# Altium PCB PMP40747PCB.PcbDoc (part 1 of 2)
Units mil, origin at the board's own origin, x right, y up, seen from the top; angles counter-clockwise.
Board outline 2952.76 x 3937.01 mil, 2 copper layers (Top Layer, Bottom Layer), stack 62 mil thick; 109 components, 53 nets, 257 pads, 138 vias.
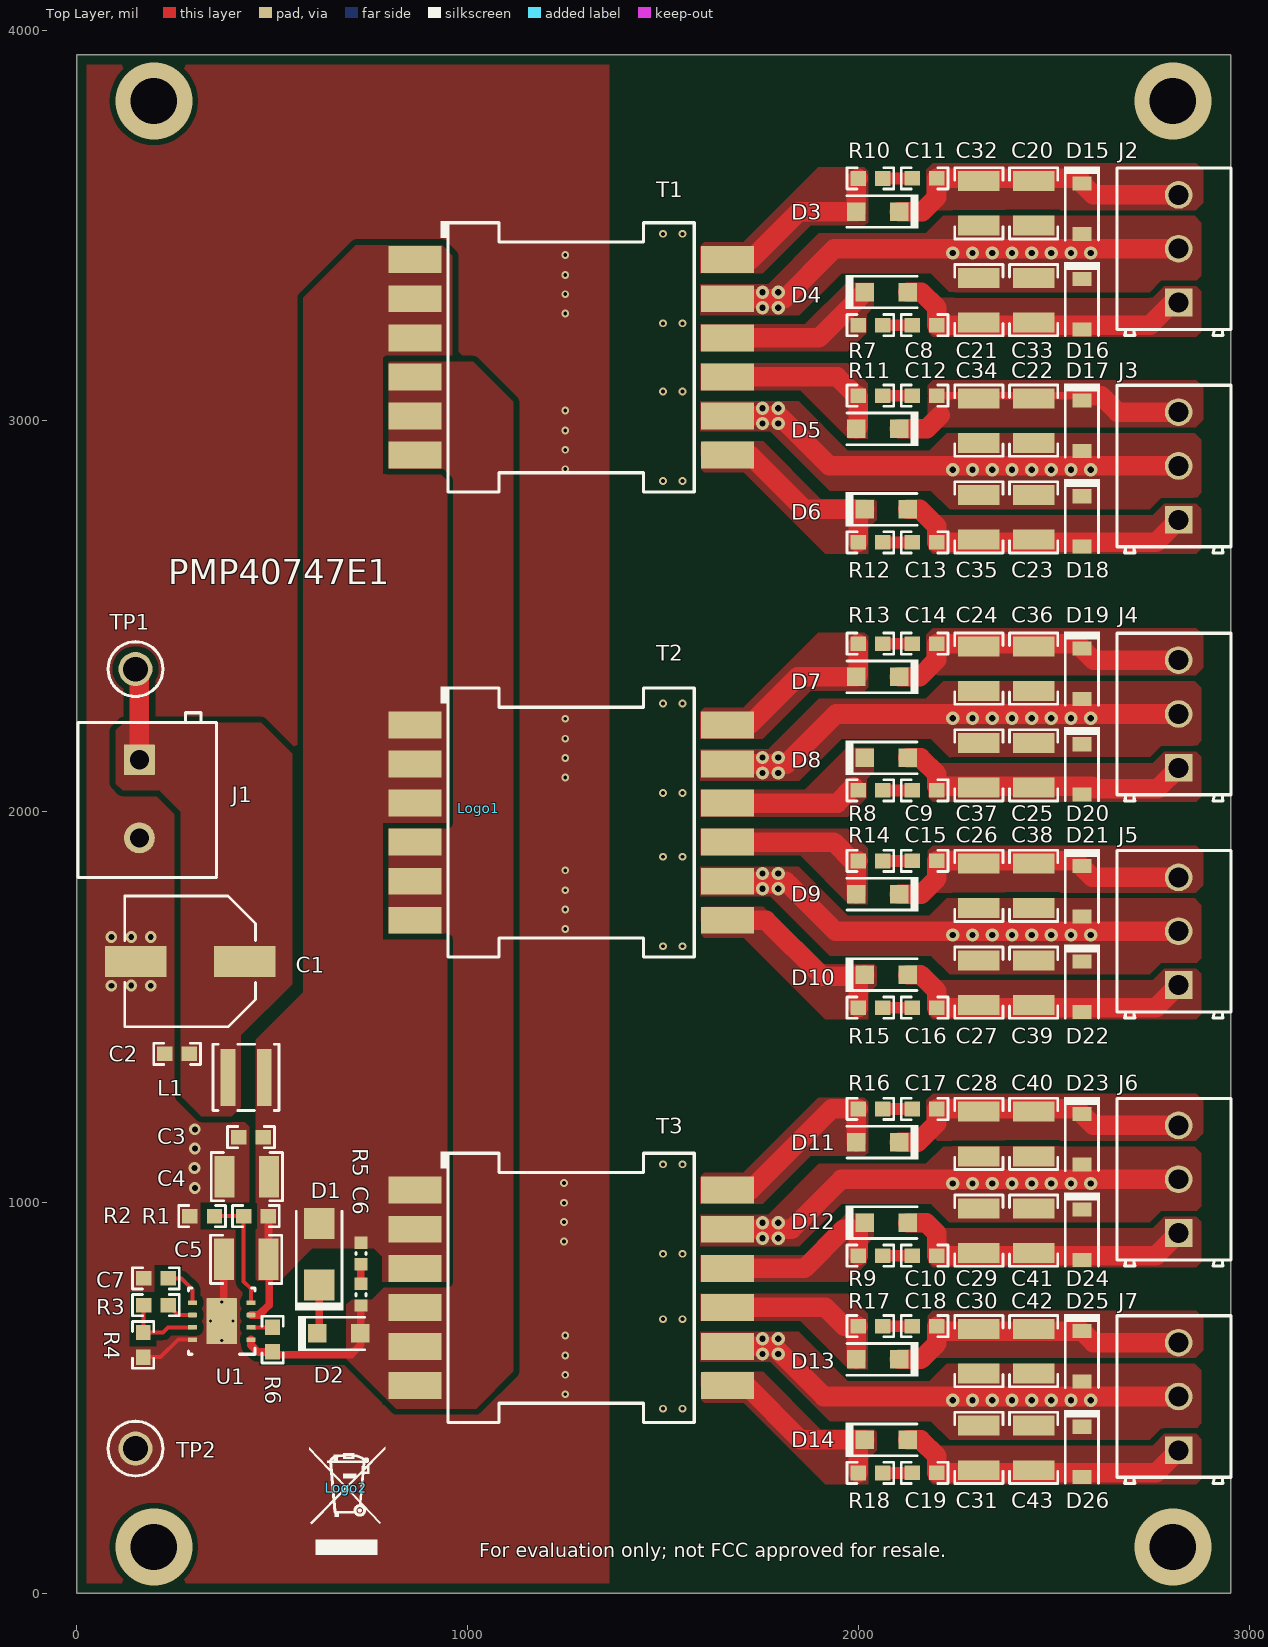
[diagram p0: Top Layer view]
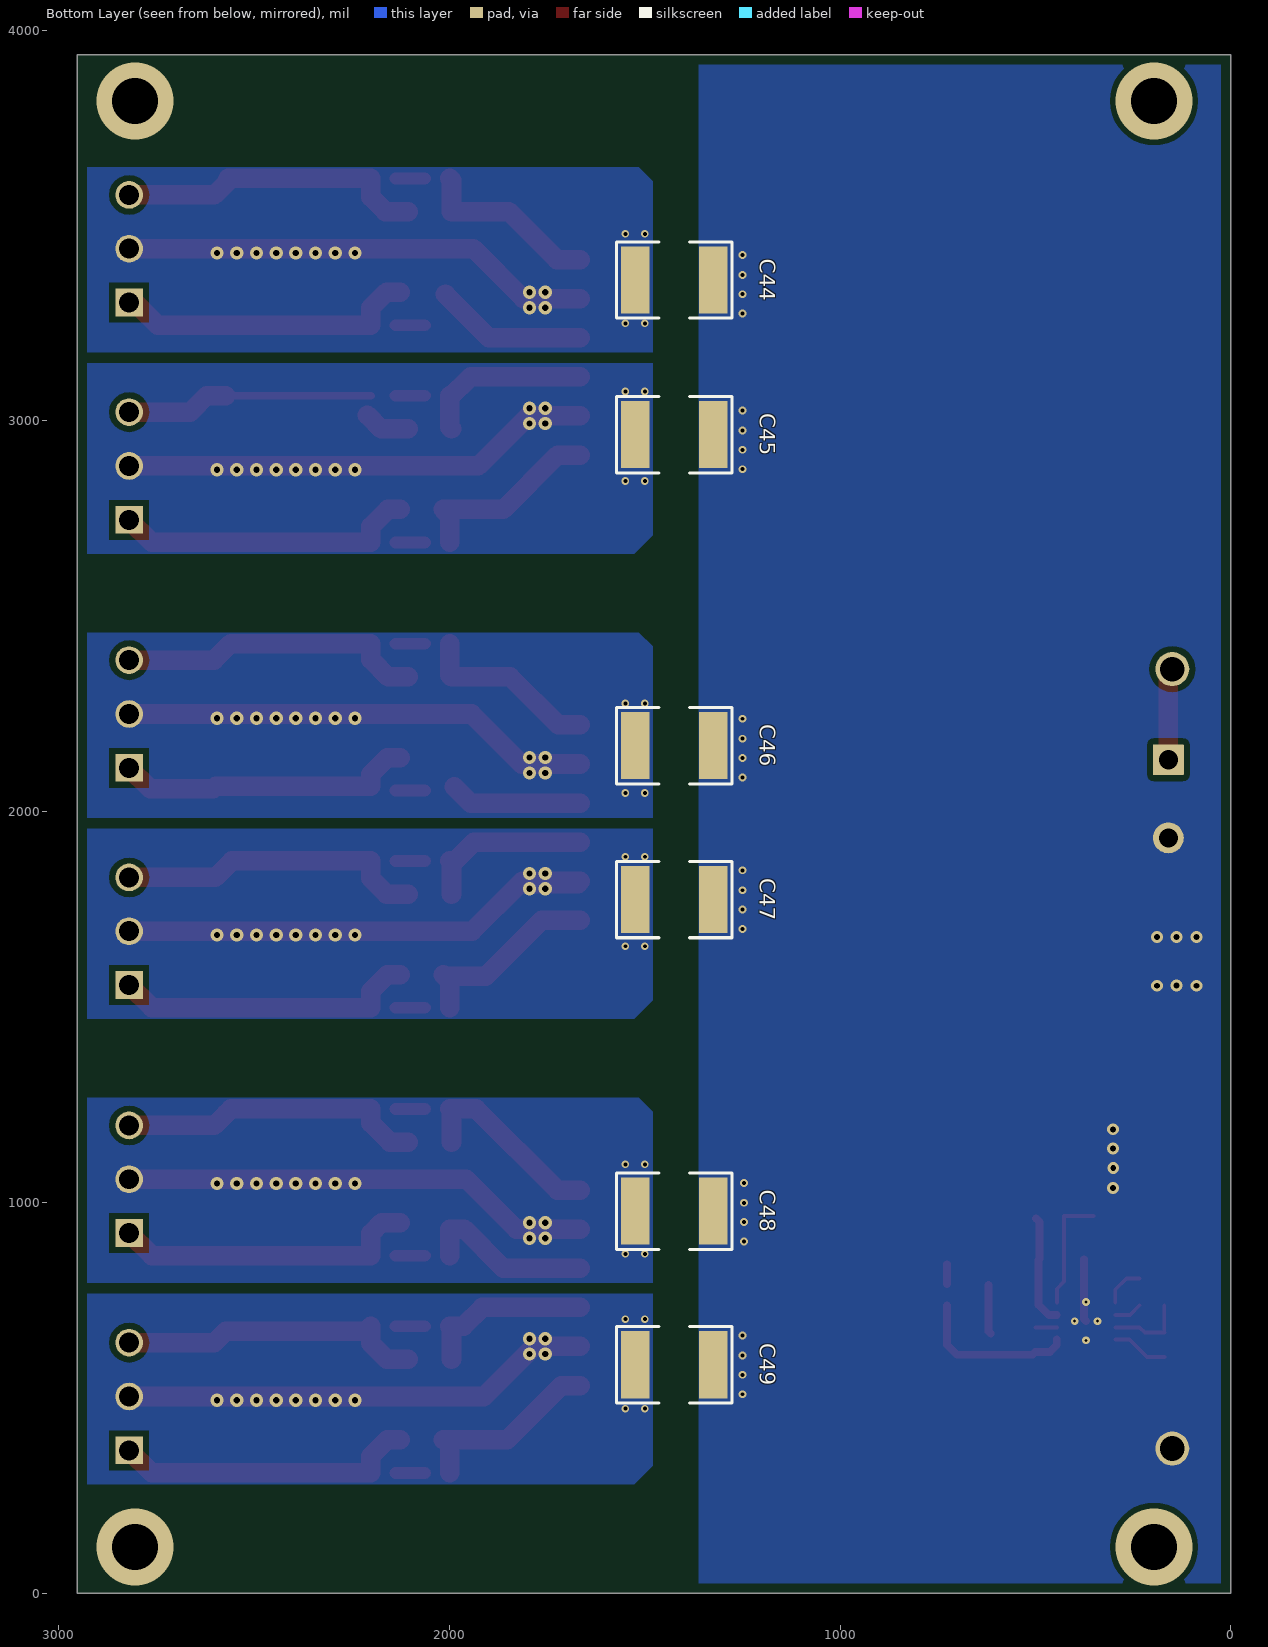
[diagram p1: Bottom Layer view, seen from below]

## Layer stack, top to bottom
Top Solder: solder mask 0.4, Solder Resist, Dk 3.5
Top Layer: signal copper 1.4
Dielectric1: core 59.2, FR-4, Dk 4.8
Bottom Layer: signal copper 1.4
Bottom Solder: solder mask 0.4, Solder Resist, Dk 3.5

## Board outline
0,0 0,3937.01 2952.76,3937.01 2952.76,0

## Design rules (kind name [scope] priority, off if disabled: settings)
AcuteAngle [All] p1: minimum=4.50000000000000E+0001 checktracksonly=FALSE
AssemblyTestPointUsage [All] p1: valid=2
BoardOutlineClearance BoardOutlineClearance_MountingHoles [OnCopper and InComponentClass('Mounting Holes')] p1: gap=39.37 ignorepadtopadclearanceinfootprint=FALSE
BoardOutlineClearance BoardOutlineClearance_Poly [OnCopper and IsPoly] p2: gap=25 ignorepadtopadclearanceinfootprint=FALSE
BoardOutlineClearance [OnCopper and Not InComponentClass('Logo') and not InComponentClass('FiducialMark') and not InRegion(1000,500,4000,800) and not InPoly] p3: gap=75 ignorepadtopadclearanceinfootprint=FALSE
Clearance Clearance_Keepouts [((IsTrack Or IsArc) And Not InPoly) And IsFree and IsKeepOut vs ((IsTrack Or IsArc) And Not InPoly) And IsFree and IsKeepOut] p1: gap=0 ignorepadtopadclearanceinfootprint=FALSE
Clearance Clearance_Poly [InPolygon] p2: gap=15 ignorepadtopadclearanceinfootprint=TRUE
Clearance Clearance_FiducialMark [IsKeepOut and InComponentClass('FiducialMark') vs IsPad and InComponentClass('FiducialMark')] p3: gap=0 ignorepadtopadclearanceinfootprint=FALSE
Clearance [All] p4: gap=7.87 ignorepadtopadclearanceinfootprint=TRUE
ComponentClearance ComponentClearance_MountingHoles_FiducialMarks [InComponentClass('Mounting Holes') vs InComponentClass('FiducialMark')] p1: gap=50 collisioncheckmode=3 verticalgap=10 showdistances=FALSE
ComponentClearance ComponentClearance_Shunt [InComponentClass('Header') vs InComponentClass('Shunt')] p2: gap=0 collisioncheckmode=3 verticalgap=0 showdistances=FALSE
ComponentClearance ComponentClearance_Logo [InComponentClass('Logo')] p3: gap=50 collisioncheckmode=3 verticalgap=10 showdistances=FALSE
ComponentClearance ComponentClearance_ScrewToNut [(HasFootprint('NY PMS 440 0025 PH')) vs (HasFootprint('Keystone_1902C'))] p4: gap=5 collisioncheckmode=3 verticalgap=10 showdistances=FALSE
ComponentClearance ComponentClearance_MountingHoles [InComponentClass('Mounting Holes')] p5: gap=250 collisioncheckmode=3 verticalgap=100000 showdistances=FALSE
ComponentClearance ComponentClearance_SmallPassives [HasFootprint('0201*') or HasFootprint('0402*') or HasFootprint('0508') or HasFootprint('0603*') or HasFootprint('0612') or HasFootprint('0805*') or HasFootprint('0815*') or HasFootprint('0830*') or HasFootprint('1206*') or HasFootprint('1210*') or HasFootprint('1808*') or HasFootprint('1812*') or HasFootprint('1825*') or HasFootprint('2010*') or HasFootprint('2220*') or HasFootprint('2225*') or HasFootprint('2512*') or HasFootprint('2728*') or HasFootprint('3518*') vs HasFootprint('0201*') or HasFootprint('0402*') or HasFootprint('0508') or HasFootprint('0603*') or HasFootprint('0612') or HasFootprint('0805*') or HasFootprint('0815*') or HasFootprint('0830*') or HasFootprint('1206*') or HasFootprint('1210*') or HasFootprint('1808*') or HasFootprint('1812*') or HasFootprint('1825*') or HasFootprint('2010*') or HasFootprint('2220*') or HasFootprint('2225*') or HasFootprint('2512*') or HasFootprint('2728*') or HasFootprint('3518*')] p6: gap=5 collisioncheckmode=3 verticalgap=5 showdistances=FALSE
ComponentClearance ComponentClearance_THtoSMT [IsThruComponent vs IsSMTComponent] p7: gap=40 collisioncheckmode=3 verticalgap=30 showdistances=FALSE
ComponentClearance ComponentClearance_THtoTH [IsThruComponent vs IsThruComponent] p8: gap=30 collisioncheckmode=3 verticalgap=30 showdistances=FALSE
ComponentClearance [All] p9: gap=5 collisioncheckmode=3 verticalgap=5 showdistances=FALSE
DiffPairsRouting [All] p1: maxlimit=100 minlimit=10 mostfreqgap=10 toplayer_minwidth=15 toplayer_maxwidth=15 toplayer_prefwidth=15 bottomlayer_minwidth=15 bottomlayer_maxwidth=15 bottomlayer_prefwidth=15 maxuncoupledlength=1000
FabricationTestPointUsage TestPointUsage [All] p1: valid=2 allowmultiple=FALSE
FabricationTestpoint Testpoint [All] p1: side=3 testpointundercomponent=TRUE minsize=40 maxsize=100 preferedsize=60 minholesize=0 maxholesize=40 preferedholesize=32 testpointgrid=1 allowsidetop=TRUE allowsidebottom=TRUE usegrid=TRUE gridtolerance=0.01
FanoutControl Fanout_LCC [IsLCC] p1: bgadir=Out bgaviamode=Centered fanoutstyle=Auto fanoutdirection=Alternating viagrid=1 // Fanout_LCC (Default Rule)
FanoutControl Fanout_BGA [IsBGA] p2: bgadir=Out bgaviamode=Centered fanoutstyle=Auto fanoutdirection=Alternating viagrid=1 // Fanout_BGA (Default Rule)
FanoutControl Fanout_Default [All] p4: bgadir=Out bgaviamode=Centered fanoutstyle=Auto fanoutdirection=Alternating viagrid=1 // Fanout_Default (Default Rule)
FanoutControl Fanout_Small [(CompPinCount < 5)] p5: bgadir=Out bgaviamode=Centered fanoutstyle=Auto fanoutdirection=OutThenIn viagrid=1 // Fanout_Small (Default Rule)
HoleSize [All] p1: absolutevalues=TRUE maxlimit=251 minlimit=7.87 maxpercent=80.000 minpercent=20.000
MinimumAnnularRing MinimumAnnularRing_ThermalPadVias [IsVia and InAnyComponent] p1: minimumring=5.91
MinimumAnnularRing [All] p2: minimumring=7.87
MinimumSolderMaskSliver MinimumSolderMaskSliver_Logo [InComponentClass('Logo') vs InComponentClass('Logo')] p1: minsoldermaskwidth=0.7
MinimumSolderMaskSliver [All] p2: minsoldermaskwidth=3.94
PlaneConnect [All] p1: planeconnectstyle=Relief reliefexpansion=10 reliefentries=4 reliefconductorwidth=10 reliefairgap=10
PolygonConnect [All] p1: connectstyle=Direct reliefconductorwidth=10 reliefentries=4 polygonreliefangle="90 Angle" airgapwidth=10
RoutingVias ThermalPadVias [IsVia and InAnyComponent] p1: holewidth=7.87 width=19.68 viastyle="Through Hole" minholewidth=7.87 minwidth=19.68 maxholewidth=12.99 maxwidth=23.62
RoutingVias [All] p2: holewidth=16 width=34 viastyle="Through Hole" minholewidth=7.87 minwidth=26 maxholewidth=40 maxwidth=65
SilkToBoardRegionClearance [Not ((IsComment or IsDesignator) And (Hide <> 'False')) and not InRegion(1000,500,4000,800)] p1:
SilkToSilkClearance SilkToSilkClearance_Pb-FreeLogo [(HasFootprint('Pb-Free_Overlay_Medium') OR HasFootprint('Pb-Free_Overlay_Small')) vs (HasFootprint('Pb-Free_Overlay_Medium') OR HasFootprint('Pb-Free_Overlay_Small'))] p1: silktosilkclearance=0
SilkToSilkClearance [All] p2: silktosilkclearance=3.94
SilkToSolderMaskClearance SilkToComponentPadClearance [(IsPad or IsFill or IsRegion) and InAnycomponent] p1: minsilkscreentomaskgap=5 clearancetoexposedcopper=TRUE
SilkToSolderMaskClearance "Silk to Solder Mask Opening" [All] p2: minsilkscreentomaskgap=3.94 clearancetoexposedcopper=FALSE
SolderMaskExpansion [All] p1: expansion=1.97
UnRoutedNet [All] p1: checkbadconnections=TRUE
Width [All] p1: maxlimit=100 minlimit=6 preferedwidth=10 checkconnectedcopper=TRUE
14 further rules are at their usual default settings.

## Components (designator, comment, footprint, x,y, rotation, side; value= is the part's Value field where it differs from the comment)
C1 "EEE-FK1E221P" SM_RADIAL_F 290.02,1616.65 r180 top value=220uF
C2 "CGA3E2X7R1H104K080AA" 0603 256.58,1380 r180 top value=0.1uF
C3 "CGA3E2X7R1H104K080AA" 0603 445.53,1166.94 r180 top value=0.1uF
C4 "UMJ325KB7106KMHT" 1210_270 435,1065.94 r180 top value=10uF
C5 "UMJ325KB7106KMHT" 1210_270 433.07,854.42 r180 top value=10uF
C6 "AC0603JRNPOYBN220" 0603L 726.67,763.87 r270 top value=22pF
C7 "CGA3E2X7R1H473K080AA" 0603 202.2,805.55 r180 top value=0.047uF
C8 "CGA3E2X7R2A102K080AA" 0603 2169.62,3245.28 r180 top value=1000pF
C9 "CGA3E2X7R2A102K080AA" 0603 2169.62,2054.46 r180 top value=1000pF
C10 "CGA3E2X7R2A102K080AA" 0603 2169.62,863.58 r180 top value=1000pF
C11 "CGA3E2X7R2A102K080AA" 0603 2169.62,3620.82 r180 top value=1000pF
C12 "CGA3E2X7R2A102K080AA" 0603 2169.62,3064.78 r180 top value=1000pF
C13 "CGA3E2X7R2A102K080AA" 0603 2169.62,2689.24 r180 top value=1000pF
C14 "CGA3E2X7R2A102K080AA" 0603 2169.62,2429.94 r180 top value=1000pF
C15 "CGA3E2X7R2A102K080AA" 0603 2169.62,1873.97 r180 top value=1000pF
C16 "CGA3E2X7R2A102K080AA" 0603 2169.62,1498.43 r180 top value=1000pF
C17 "CGA3E2X7R2A102K080AA" 0603 2169.62,1239.12 r180 top value=1000pF
C18 "CGA3E2X7R2A102K080AA" 0603 2169.62,683.09 r180 top value=1000pF
C19 "CGA3E2X7R2A102K080AA" 0603 2169.62,307.61 r180 top value=1000pF
C20 "TMK325B7226MM-PR" 1210_270 2448.79,3556.82 r90 top value=22uF
C21 "TMK325B7226MM-PR" 1210_270 2308.34,3309.21 r270 top value=22uF
C22 "TMK325B7226MM-PR" 1210_270 2448.79,3000.78 r90 top value=22uF
C23 "TMK325B7226MM-PR" 1210_270 2448.79,2753.17 r270 top value=22uF
C24 "TMK325B7226MM-PR" 1210_270 2308.34,2366 r90 top value=22uF
C25 "TMK325B7226MM-PR" 1210_270 2448.79,2118.4 r270 top value=22uF
C26 "TMK325B7226MM-PR" 1210_270 2308.34,1809.97 r90 top value=22uF
C27 "TMK325B7226MM-PR" 1210_270 2308.34,1562.36 r270 top value=22uF
C28 "TMK325B7226MM-PR" 1210_270 2308.34,1175.19 r90 top value=22uF
C29 "TMK325B7226MM-PR" 1210_270 2308.34,927.58 r270 top value=22uF
C30 "TMK325B7226MM-PR" 1210_270 2308.34,619.15 r90 top value=22uF
C31 "TMK325B7226MM-PR" 1210_270 2308.34,371.54 r270 top value=22uF
C32 "TMK325B7226MM-PR" 1210_270 2308.34,3556.82 r90 top value=22uF
C33 "TMK325B7226MM-PR" 1210_270 2448.79,3309.21 r270 top value=22uF
C34 "TMK325B7226MM-PR" 1210_270 2308.34,3000.78 r90 top value=22uF
C35 "TMK325B7226MM-PR" 1210_270 2308.34,2753.17 r270 top value=22uF
C36 "TMK325B7226MM-PR" 1210_270 2448.79,2366 r90 top value=22uF
C37 "TMK325B7226MM-PR" 1210_270 2308.34,2118.4 r270 top value=22uF
C38 "TMK325B7226MM-PR" 1210_270 2448.79,1809.97 r90 top value=22uF
C39 "TMK325B7226MM-PR" 1210_270 2448.79,1562.36 r270 top value=22uF
C40 "TMK325B7226MM-PR" 1210_270 2448.79,1175.19 r90 top value=22uF
C41 "TMK325B7226MM-PR" 1210_270 2448.79,927.58 r270 top value=22uF
C42 "TMK325B7226MM-PR" 1210_270 2448.79,619.15 r90 top value=22uF
C43 "TMK325B7226MM-PR" 1210_270 2448.79,371.54 r270 top value=22uF
C44 "C1812C102KHRACAUTO" 1812_180 1425,3361 r180 bottom value=1000pF
C45 "C1812C102KHRACAUTO" 1812_180 1425,2965 r180 bottom value=1000pF
C46 "C1812C102KHRACAUTO" 1812_180 1425,2169 r180 bottom value=1000pF
C47 "C1812C102KHRACAUTO" 1812_180 1425,1775 r180 bottom value=1000pF
C48 "C1812C102KHRACAUTO" 1812_180 1425,977.54 r180 bottom value=1000pF
C49 "C1812C102KHRACAUTO" 1812_180 1425,584.51 r180 bottom value=1000pF
D1 "3SMAJ5936B-TP" SMA 620.09,867.54 r90 top value=30V
D2 "PMEG60T30ELRX" SOD-123W 670,664.64 r0 top value=60V
D3 "PMEG6010CEH,115" SOD-123F 2049.95,3536.04 r180 top value=60V
D4 "PMEG6010CEH,115" SOD-123F 2071.45,3329.99 r0 top value=60V
D5 "PMEG6010CEH,115" SOD-123F 2049.95,2980.01 r180 top value=60V
D6 "PMEG6010CEH,115" SOD-123F 2071.45,2773.95 r0 top value=60V
D7 "PMEG6010CEH,115" SOD-123F 2049.95,2345.23 r180 top value=60V
D8 "PMEG6010CEH,115" SOD-123F 2071.45,2137.61 r0 top value=60V
D9 "PMEG6010CEH,115" SOD-123F 2049.95,1789.19 r180 top value=60V
D10 "PMEG6010CEH,115" SOD-123F 2071.45,1583.14 r0 top value=60V
D11 "PMEG6010CEH,115" SOD-123F 2049.95,1154.41 r180 top value=60V
D12 "PMEG6010CEH,115" SOD-123F 2071.45,948.36 r0 top value=60V
D13 "PMEG6010CEH,115" SOD-123F 2049.95,598.38 r180 top value=60V
D14 "PMEG6010CEH,115" SOD-123F 2071.45,392.32 r0 top value=60V
D15 "DDZ16BQ-7" SOD-123 2572.35,3543.52 r270 top value=16V
D16 "DDZ8V2BQ-7" SOD-123 2572.35,3298.96 r270 top value=8.2V
D17 "DDZ16BQ-7" SOD-123 2572.35,2987.48 r270 top value=16V
D18 "DDZ8V2BQ-7" SOD-123 2572.34,2742.92 r270 top value=8.2V
D19 "DDZ16BQ-7" SOD-123 2572.35,2352.7 r270 top value=16V
D20 "DDZ8V2BQ-7" SOD-123 2572.35,2108.15 r270 top value=8.2V
D21 "DDZ16BQ-7" SOD-123 2572.35,1796.67 r270 top value=16V
D22 "DDZ8V2BQ-7" SOD-123 2572.35,1552.11 r270 top value=8.2V
D23 "DDZ16BQ-7" SOD-123 2572.34,1161.89 r270 top value=16V
D24 "DDZ8V2BQ-7" SOD-123 2572.35,917.33 r270 top value=8.2V
D25 "DDZ16BQ-7" SOD-123 2572.35,606.08 r270 top value=16V
D26 "DDZ8V2BQ-7" SOD-123 2572.35,361.29 r270 top value=8.2V
J1 "ED120/2DS" On-Shore_ED120_2DS 160,2032.8 r270 top
J2 "691214000000" Wurth_691214110003 2819.77,3440.89 r90 top
J3 "691214000000" Wurth_691214110003 2819.77,2884.85 r90 top
J4 "691214000000" Wurth_691214110003 2819.77,2250.07 r90 top
J5 "691214000000" Wurth_691214110003 2819.77,1694.04 r90 top
J6 "691214000000" Wurth_691214110003 2819.77,1059.26 r90 top
J7 "691214000000" Wurth_691214110003 2819.77,503.22 r90 top
L1 "XAL4030-332MEB" XAL4030 433.07,1320 r0 top value=3.3uH
Logo1 "FCC disclaimer" FCC_disclaimer 1028.98,2008.28 r0 top
Logo2 "WEEE logo" WEEE_Minimum 690,270 r0 top
R1 "CRCW0603140KFKEA" 0603 458.23,964.94 r0 top value=140k
R2 "CRCW060328K0FKEA" 0603 320.57,964.94 r0 top value=28.0k
R3 "CRCW0603348KFKEA" 0603 202.2,736.79 r0 top value=348k
R4 "CRCW060312K1FKEA" 0603 169.48,635.45 r90 top value=12.1k
R5 "CRCW0603100RFKEA" 0603L 726.67,869.18 r90 top value=100
R6 "CRCW0603232KFKEA" 0603 500.73,648.83 r270 top value=232k
R7 "CRCW060310R0FKEAHP" 0603 2030.94,3245.21 r0 top value=10.0
R8 "CRCW060310R0FKEAHP" 0603 2030.94,2054.4 r0 top value=10.0
R9 "CRCW060310R0FKEAHP" 0603 2030.94,863.58 r0 top value=10.0
R10 "CRCW060310R0FKEAHP" 0603 2030.94,3620.75 r0 top value=10.0
R11 "CRCW060310R0FKEAHP" 0603 2030.94,3064.72 r0 top value=10.0
R12 "CRCW060310R0FKEAHP" 0603 2030.94,2689.17 r0 top value=10.0
R13 "CRCW060310R0FKEAHP" 0603 2030.94,2429.94 r0 top value=10.0
R14 "CRCW060310R0FKEAHP" 0603 2030.94,1873.9 r0 top value=10.0
R15 "CRCW060310R0FKEAHP" 0603 2030.94,1498.36 r0 top value=10.0
R16 "CRCW060310R0FKEAHP" 0603 2030.94,1239.12 r0 top value=10.0
R17 "CRCW060310R0FKEAHP" 0603 2030.94,683.09 r0 top value=10.0
R18 "CRCW060310R0FKEAHP" 0603 2030.94,307.54 r0 top value=10.0
T1 "750344812" EFD15 1265.2,3162.87 r0 top value=45uH
T2 "750344812" EFD15 1265.2,1972.06 r0 top value=45uH
T3 "750344812" EFD15 1265.2,781.24 r0 top value=45uH
TP1 "5010" Keystone5010 150,2365 r0 top
TP2 "5011" Keystone5011 150,370 r0 top
U1 "LM25184QNGURQ1" NGU0008C 370.73,696.07 r180 top

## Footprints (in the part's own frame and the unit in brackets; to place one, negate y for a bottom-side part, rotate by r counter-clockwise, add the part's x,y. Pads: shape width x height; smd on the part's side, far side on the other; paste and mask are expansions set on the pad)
0603 [mm] "0603 from SM-752 data"
  rect 1x0.95 smd: 1(-0.8,0) 2(0.8,0)
  silkscreen extent -1.52,-0.69 1.52,0.69, body extent -0.87,-0.47 0.87,0.47, height 1
0603L [mm] "0603 from SM-752 data"
  rect 0.8x0.85 smd: 1(-0.7,0) 2(0.7,0)
  silkscreen extent -0.07,-0.33 0.07,0.33, body extent -0.87,-0.47 0.87,0.47, height 1
1210_270 [mm] "1210"
  rect 1.3x2.7 smd: 1(-1.45,0) 2(1.45,0)
  silkscreen extent -2.32,-1.57 2.32,1.57, body extent -1.7,-1.35 1.7,1.35, height 2.7
1812_180 [mm] "SMT, 2-Leads, Body 4.5x3.2mm"
  rect 1.85x4.36 smd: 1(-2.53,0) 2(2.53,0)
  silkscreen extent -3.75,-2.48 3.75,2.48, body extent -2.43,-1.75 2.42,1.75, height 1.8
EFD15 [mm] "SMT, 12-Leads, Body 17.5x16mm, Pitch 2.54mm"
  rect 3.43x1.75 smd: 1(-10.155,6.35) 2(-10.155,3.81) 3(-10.155,1.27) 4(-10.155,-1.27) 5(-10.155,-3.81) 6(-10.155,-6.35) 7(10.155,-6.35) 8(10.155,-3.81) 9(10.155,-1.27) 10(10.155,1.27) 11(10.155,3.81) 12(10.155,6.35)
  silkscreen extent -8.5,-8.75 8,8.85, body extent -11.05,-8.75 11.05,8.75, height 8.3
FCC_disclaimer [mil]
Keystone5010 [mil] "Keystone Multipurpose loops"
  round 87 hole 63: 1(0,0)
  silkscreen extent -70,-70 70,70, body extent -63,-63 63,62, height 319
Keystone5011 [mil] "Keystone Multipurpose loops"
  round 87 hole 63: 1(0,0)
  silkscreen extent -70,-70 70,70, body extent -63,-63 63,62, height 319
NGU0008C [mm] "SON, 8-Leads, Body 4x4mm, Pitch 0.8mm"
  rrect33% 0.6x0.3 smd: 1(-1.9,1.2) 2(-1.9,0.4) 3(-1.9,-0.4) 4(-1.9,-1.2) 5(1.9,-1.2) 6(1.9,-0.4) 7(1.9,0.4) 8(1.9,1.2)
  rrect8% 1.75x1.31 on Top Paste: 9(0,0.755) 9(0,-0.755)
  rrect5% 1.98x3 smd paste-1.5: 9(0,0)
  silkscreen extent -2.15,-2.15 2.15,2.15, body extent -2,-2 2,2, height 0.77
On-Shore_ED120_2DS [mm] "ONSHORE"
  rrect5% 2x2 hole 1.25: 1(-2.54,0)
  round 2 hole 1.25: 2(2.54,0)
  silkscreen extent -5.6,-4 5.12,5, body extent -5.78,-4 5.08,5, height 13
SM_RADIAL_F [mm] "8 x 10.2mm:  Panasonic F"
  rect 4x2 smd: 1(-3.55,0) 2(3.55,0)
  silkscreen extent -4.25,-4.25 4.25,4.25, body extent -4.25,-4.25 4.25,4.25, height 10.5
SMA [mm] "Molded Diode, 2-Leads, Body 4.3x2.6mm, IPC Medium Density, based on OnSemi component dimensions and land pattern"
  rect 2x2 smd: 1(-2,0) 2(2,0)
  silkscreen extent -3.66,-1.57 2.79,1.57, body extent -2.6,-1.3 2.6,1.3, height 2.42
SOD-123 [mm] "On Semi recommended land pattern"
  rect 0.915x1.22 smd: 1(-1.637,0) 2(1.637,0)
  silkscreen extent -2.74,-1.17 2.03,1.17, body extent -1.93,-0.9 1.93,0.9, height 1.35
SOD-123F [mm] "NXP recommended land pattern"
  rect 1.2x1.2 smd paste-0.05: 1(-1.4,0) 2(1.4,0)
  silkscreen extent -2.64,-1.12 2.01,1.12, body extent -1.8,-0.85 1.8,0.85, height 1.2
SOD-123W [mm] "NXP recommended land pattern"
  rect 1.2x1.2 smd paste-0.05: 1(-1.4,0) 2(1.4,0)
  silkscreen extent -2.64,-1.14 1.68,1.14, body extent -1.85,-0.95 1.85,0.95, height 1.1
WEEE_Minimum [mil] "WEEElie bin"
  silkscreen extent -95,-172 99,104
Wurth_691214110003 [mm] "Terminal Block, 3.5mm, 3x1, TH"
  rect 1.8x1.8 hole 1.3: 1(-3.5,0)
  round 1.8 hole 1.3: 2(0,0) 3(3.5,0)
  silkscreen extent -5.65,-3.4 5.25,4, body extent -5.65,-3.4 5.25,4, height 8.5
XAL4030 [mil] "Coilcraft XAL4030 7/18/12"
  rect 38x146 smd: 1(-46.5,0) 2(46.5,0)
  silkscreen extent -84,-84 84,84, body extent -84,-84 84,84, height 122

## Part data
C1: "CAP, AL, 220 µF, 25 V, +/- 20%, 0.16 ohm, SMD", Cap_Case=F, Manufacturer=Panasonic, Supplier Part Number 1=PCE3800CT-ND, Tolerance_%=20, Value1="0.16 ohm", Value2=25V, ValueDisplayed=220µF
C2 C3: library part CMP-0007078-3, "CAP, CERM, 0.1 uF, 50 V, +/- 10%, X7R, AEC-Q200 Grade 1, 0603", Cap_Case=0603, Manufacturer=TDK, Supplier Part Number 1=445-5666-1-ND, TempCo=X7R, Tolerance_%=10%, Value1="0.0296 ohm", Value2=50V, ValueDisplayed=0.1uF
C4 C5: library part CMP-0009257-2, "CAP, CERM, 10 uF, 50 V, +/- 10%, X7R, AEC-Q200 Grade 1, 1210", Cap_Case=1210, Manufacturer="Taiyo Yuden", Supplier Part Number 1=587-4279-1-ND, TempCo=X7R, Tolerance_%=10%, Value1=Unknown, Value2=50V, ValueDisplayed=10uF
C6: library part CMP-0080060-1, "CAP, CERM, 22 pF, 250 V,+/- 5%, C0G/NP0, AEC-Q200 Grade 1, 0603", Cap_Case=0603, Manufacturer="Yageo America", Supplier Part Number 1=311-3095-1-ND, TempCo=C0G/NP0, Tolerance_%=5%, Value2=250V, ValueDisplayed=22pF
C7: library part CMP-0007079-2, "CAP, CERM, 0.047 uF, 50 V, +/- 10%, X7R, AEC-Q200 Grade 1, 0603", Cap_Case=0603, Manufacturer=TDK, Supplier Part Number 1=445-5664-1-ND, TempCo=X7R, Tolerance_%=10%, Value1="0.049007 ohm", Value2=50V, ValueDisplayed=0.047uF
C8 C9 C10 C11 C12 C13 C14 C15 C16 C17 C18 C19: library part CMP-0007081-1, "CAP, CERM, 1000 pF, 100 V, +/- 10%, X7R, AEC-Q200 Grade 1, 0603", Cap_Case=0603, Manufacturer=TDK, Supplier Part Number 1=445-5806-1-ND, TempCo=X7R, Tolerance_%=10%, Value1="1.97137 ohm", Value2=100V, ValueDisplayed=1000pF
C20 C21 C22 C23 C24 C25 C26 C27 C28 C29 C30 C31 C32 C33 C34 C35 C36 C37 C38 C39 C40 C41 C42 C43: library part CMP-0009255-2, "CAP, CERM, 22 uF, 25 V, +/- 10%, X7R, AEC-Q200 Grade 1, 1210", Cap_Case=1210, Manufacturer="Taiyo Yuden", TempCo=X7R, Tolerance_%=10%, Value1=Unknown, Value2=25V, ValueDisplayed=22uF
C44 C45 C46 C47 C48 C49: library part CMP-0076765-1, "CAP, CERM, 1000 pF, 3000 V,+/- 10%, X7R, 1812", Cap_Case=1812, Manufacturer=Kemet, TempCo=X7R, Tolerance_%=10%, Value2=3000V, ValueDisplayed=1000pF
D1: library part CMP-0005515-1, "Diode, Zener, 30 V, 3 W, SMA", Manufacturer="Micro Commercial Components", Power_W=3W, Supplier Part Number 1=3SMAJ5936B-TPMSCT-ND
D2: library part CMP-0085903-1, "Diode, Schottky, 60 V, 3 A, AEC-Q101, SOD-123W", Manufacturer=Nexperia, Value1=3A, Value2=0.62V
D3 D4 D5 D6 D7 D8 D9 D10 D11 D12 D13 D14: library part CMP-0028377-2, "Diode, Schottky, 60 V, 1 A, SOD-123F", Manufacturer=Nexperia, Value1=1A, Value2=0.57V
D15 D17 D19 D21 D23 D25: library part CMP-0085138-1, "Diode, Zener, 16 V, 500 mW, AEC-Q101, SOD-123", Manufacturer="Diodes Inc.", Power_W=500mW, Value1=0.5W
D16 D18 D20 D22 D24 D26: library part CMP-0085111-1, "Diode, Zener, 8.2 V, 500 mW, AEC-Q101, SOD-123", Manufacturer="Diodes Inc.", Power_W=500mW, Value1=0.5W
J1: library part CMP-0074910-1, "Terminal Block, 5.08 mm, 2x1, Brass, TH", Color=Blue, Current_A=15A, Manufacturer="On-Shore Technology", Supplier Part Number 1=ED1609-ND, Voltage_V=300V
J2 J3 J4 J5 J6 J7: library part CMP-0054824-1, "Terminal Block, 3.5mm, 3x1, Tin, TH", Color=Green, Current_A=10A, Manufacturer="Wurth Elektronik", Supplier Part Number 1=732-2748-ND, Voltage_V=300V
L1: library part CMP-0060989-1, "Inductor, Shielded, Composite, 3.3 uH, 5.5 A, 0.026 ohm, SMD", Manufacturer=Coilcraft, Supplier Part Number 1=994-XAL4030-332MEB, Value1="0.026 ohm", Value2=5.5A, ValueDisplayed=3.3uH
Logo1: library part CMP-0074847-1, "FCC_disclaimer"
Logo2: library part CMP-0074769-1
R1: library part CMP-0022048-4, "RES, 140 k, 1%, 0.1 W, AEC-Q200 Grade 0, 0603", Manufacturer=Vishay-Dale, Power_W=100mW, Supplier Part Number 1=541-140KHCT-ND, TempCo="100 ppm/C", Tolerance_%=1%, Value2=0.1W, Value_Code=140k
R2: library part CMP-0022260-4, "RES, 28.0 k, 1%, 0.1 W, AEC-Q200 Grade 0, 0603", Manufacturer=Vishay-Dale, Power_W=100mW, Supplier Part Number 1=541-28.0KHCT-ND, TempCo="100 ppm/C", Tolerance_%=1%, Value2=0.1W, Value_Code=28k0, ValueDisplayed=28.0k
R3: library part CMP-0022344-4, "RES, 348 k, 1%, 0.1 W, AEC-Q200 Grade 0, 0603", Manufacturer=Vishay-Dale, Power_W=100mW, Supplier Part Number 1=541-348KHCT-ND, TempCo="100 ppm/C", Tolerance_%=1%, Value2=0.1W, Value_Code=348k
R4: library part CMP-0022030-4, "RES, 12.1 k, 1%, 0.1 W, AEC-Q200 Grade 0, 0603", Manufacturer=Vishay-Dale, Power_W=100mW, Supplier Part Number 1=541-12.1KHCT-ND, TempCo="100 ppm/C", Tolerance_%=1%, Value2=0.1W, Value_Code=12k1, ValueDisplayed=12.1k
R5: library part CMP-0021991-4, "RES, 100, 1%, 0.1 W, AEC-Q200 Grade 0, 0603", Manufacturer=Vishay-Dale, Power_W=100mW, Supplier Part Number 1=541-100HCT-ND, TempCo="100 ppm/C", Tolerance_%=1%, Value2=0.1W, Value_Code=100R, ValueDisplayed=100
R6: library part CMP-0022224-4, "RES, 232 k, 1%, 0.1 W, AEC-Q200 Grade 0, 0603", Manufacturer=Vishay-Dale, Power_W=100mW, Supplier Part Number 1=541-232KHCT-ND, TempCo="100 ppm/C", Tolerance_%=1%, Value2=0.1W, Value_Code=232k
R7 R8 R9 R10 R11 R12 R13 R14 R15 R16 R17 R18: library part CMP-0022004-4, "RES, 10.0, 1%, 0.25 W, AEC-Q200 Grade 0, 0603", Manufacturer=Vishay-Dale, Power_W=250mW, Supplier Part Number 1=541-10.0SCT-ND, TempCo="100 ppm/C", Tolerance_%=1%, Value2=0.25W, Value_Code=10R0, ValueDisplayed=10.0
T1 T2 T3: library part PMP40747, "Transformer, 45uH, SMT", Manufacturer=Wurth
TP1: library part CMP-0055147-1, "Test Point, Multipurpose, Red, TH", Color=Red, Manufacturer=Keystone, Supplier Part Number 1=36-5010-ND
TP2: library part CMP-0055148-1, "Test Point, Multipurpose, Black, TH", Color=Black, Manufacturer=Keystone, Supplier Part Number 1=36-5011-ND
U1: library part CMP-0860959-2, "42-VIN PSR Flyback DC/DC Converter with 65-V, 4-A Integrated MOSFET, NGU0008C (WSON-8)", Alternate Manufacturer="Texas Instruments"

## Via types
v1: diameter 34, hole 16, Top Layer to Bottom Layer, tented both sides, 72 vias
v2: diameter 20, hole 10, Top Layer to Bottom Layer, tented both sides, 48 vias
v3: diameter 30, hole 15, Top Layer to Bottom Layer, tented both sides, 10 vias
v4: diameter 196.85, hole 118.11, Top Layer to Bottom Layer, 4 vias
v5: diameter 19.68, hole 7.87, Top Layer to Bottom Layer, 4 vias

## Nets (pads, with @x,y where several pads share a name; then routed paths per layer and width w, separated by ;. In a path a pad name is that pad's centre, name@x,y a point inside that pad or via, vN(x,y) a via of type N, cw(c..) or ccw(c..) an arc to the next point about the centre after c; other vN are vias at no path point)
+15V_1: C11.1 C20.2 C32.2 D3.1 D15.1 J2.3 | length 799.5
  Top Layer w50: D3.1@2105.07,3536.04 2164.04,3536.04 2201.12,3573.12 C11.1@2201.12,3620.82 2566.82,3620.82 2566.82,3613.52 D15.1@2572.35,3607.99 2601.65,3578.68 J2.3@2819.77,3578.68
+15V_2: C12.1 C22.2 C34.2 D5.1 D17.1 J3.3 | length 761
  Top Layer w20: C12.1@2201.12,3064.78 2559.52,3064.78 D17.1@2572.35,3051.95
  Top Layer w50: D5.1@2105.07,2980.01 2175.01,2980.01 2210.1,3015.1 ; D17.1@2572.35,3064.78 2621.22,3064.78 2663.35,3022.65 J3.3@2819.77,3022.65
+15V_3: C14.1 C24.2 C36.2 D7.1 D19.1 J4.3 | length 791.1
  Top Layer w50: D7.1@2105.07,2345.23 2157.23,2345.23 2201.12,2389.12 C14.1@2201.12,2429.94 2560.06,2429.94 2602.13,2387.87 J4.3@2819.77,2387.87
+15V_4: C15.1 C26.2 C38.2 D9.1 D21.1 J5.3 | length 793.5
  Top Layer w50: D9.1@2105.07,1789.19 2161.19,1789.19 2201.12,1829.12 C15.1@2201.12,1873.97 2556.87,1873.97 2599,1831.83 J5.3@2819.77,1831.83
+15V_5: C17.1 C28.2 C40.2 D11.1 D23.1 J6.3 | length 788.3
  Top Layer w50: D11.1@2105.07,1154.41 2152.41,1154.41 2201.12,1203.12 C17.1@2201.12,1239.12 2559.58,1239.12 D23.1@2572.34,1226.36 2601.65,1197.06 J6.3@2819.77,1197.06
+15V_6: C18.1 C30.2 C42.2 D13.1 D25.1 J7.3 | length 793
  Top Layer w50: D13.1@2105.07,598.38 2160.38,598.38 2201.12,639.12 C18.1@2201.12,683.09 2213.66,670.55 D25.1@2572.35,670.55 2601.88,641.02 J7.3@2819.77,641.02
-8V_1: C8.1 C21.2 C33.2 D4.2 D16.2 J2.1 | length 789.1
  Top Layer w30: J2.1@2804.66,3303.09 J2.1@2819.77,3303.09
  Top Layer w50: D4.2@2126.57,3329.99 2161.11,3329.99 2201.12,3289.98 C8.1@2201.12,3245.28 2746.84,3245.28 2804.66,3303.09 J2.1@2812.22,3295.54
-8V_2: C13.1 C23.2 C35.2 D6.2 D18.2 J3.1 | length 776.3
  Top Layer w50: D6.2@2126.57,2773.95 2157.47,2773.95 2201.12,2730.31 C13.1@2201.12,2689.24 2761.95,2689.24 J3.1@2819.77,2747.06
-8V_3: C9.1 C25.2 C37.2 D8.2 D20.2 J4.1 | length 766
  Top Layer w50: D8.2@2126.57,2137.61 2159.51,2137.61 2201.12,2096 2201.12,2065.2 2598.8,2065.2 2605.1,2058.9 2766.4,2058.9 J4.1@2819.77,2112.28
-8V_4: C16.1 C27.2 C39.2 D10.2 D22.2 J5.1 | length 777.1
  Top Layer w50: D10.2@2126.57,1583.14 2158.86,1583.14 2201.12,1540.88 C16.1@2201.12,1498.43 2761.95,1498.43 J5.1@2819.77,1556.24
-8V_5: C10.1 C29.2 C41.2 D12.2 D24.2 J6.1 | length 785.9
  Top Layer w50: D12.2@2126.57,948.36 2173.64,948.36 2201.12,920.88 C10.1@2201.12,863.58 2761.89,863.58 J6.1@2819.77,921.46
-8V_6: C19.1 C31.2 C43.2 D14.2 D26.2 J7.1 | length 777.6
  Top Layer w50: D14.2@2126.57,392.32 2159.68,392.32 2201.12,350.88 C19.1@2201.12,307.61 2761.95,307.61 J7.1@2819.77,365.43
GND: C1.2 C2.2 C3.2 C4.2 C5.2 C7.2 C44.2 C45.2 C46.2 C47.2 C48.2 C49.2 J1.2 R2.1 R4.1 TP2.1 U1.8 U1.9@370.73,696.07 | length 305.6
  Top Layer w10: R4.1@169.48,603.95 214.5,603.95 259.38,648.83 U1.8@295.93,648.83
  Top Layer w20: U1.9@370.73,696.07 375.98,701.33 C5.2@375.98,854.42
  other v2: 1250,509.09 1250,558.67 1250,608.07 1250,659.09 1246.5,900 1246.5,949.59 1246.5,998.99 1246.5,1050 1250,1700 1250,1749.59 1250,1798.99 1250,1850 1250,2087.9 1250,2137.48 1250,2186.89 1250,2237.9 1250,2876.65 1250,2926.24 1250,2975.64 1250,3026.65 1250,3275 1250,3324.59 1250,3373.99 1250,3425
  other v3: 301.87,1037.1 301.14,1088.1 301.87,1138.1 301.87,1186.94 88.19,1554.34 189.19,1554.34 139.19,1555.06 88.19,1679.34 139.19,1679.34 189.19,1679.34
  other v5: 370.73,646.86 341.59,696.07 399.86,696.07 370.73,745.29
NetC1_1: C1.1 C2.1 J1.1 L1.1 TP1.1 | length 236.3
  Top Layer w50: TP1.1@150,2365 160,2355 J1.1@160,2132.8
NetC3_1: C3.1 C4.1 C5.1 D1.2 L1.2 R1.2 R5.2 T1.1 T1.2 T1.3 T2.1 T2.2 T2.3 T3.1 T3.2 T3.3 U1.3 | length 283.4
  Top Layer w20: U1.3@445.53,711.82 466.31,711.82 492.23,737.74 492.23,852.34 C5.1@490.16,854.42 490.16,950.43 R1.2@498.91,959.18
NetC6_1: C6.1 R5.1 | length 50.2
  Top Layer w20: C6.1@726.67,791.43 R5.1@726.67,841.62
NetC6_2: C6.2 D2.2 R6.2 T1.4 T1.5 T1.6 T2.4 T2.5 T2.6 T3.4 T3.5 T3.6 U1.1 | length 416.7
  Top Layer w20: U1.1@445.53,648.83 445.53,635.05 463.25,617.33 R6.2@500.73,617.33 508.06,610 701.22,610 726.67,635.45 C6.2@726.67,736.31
NetC7_1: C7.1 U1.5 | length 107.7
  Top Layer w10: C7.1@233.69,805.55 267.23,805.55 295.93,776.85 U1.5@295.93,743.32
NetC8_2: C8.2 R7.2 | length 75.7
  Top Layer w30: R7.2@2062.43,3245.21 2138.06,3245.21 C8.2@2138.13,3245.28
NetC9_2: C9.2 R8.2 | length 75.7
  Top Layer w30: R8.2@2062.43,2054.4 2138.06,2054.4 C9.2@2138.13,2054.46
NetC10_2: C10.2 R9.2 | length 75.7
  Top Layer w30: R9.2@2062.43,863.58 C10.2@2138.13,863.58
NetC11_2: C11.2 R10.2 | length 75.7
  Top Layer w30: R10.2@2062.43,3620.75 C11.2@2138.13,3620.82 C11.2@2138.13,3620.82
NetC12_2: C12.2 R11.2 | length 75.7
  Top Layer w30: R11.2@2062.43,3064.72 2138.06,3064.72 C12.2@2138.13,3064.78
NetC13_2: C13.2 R12.2 | length 75.7
  Top Layer w20: C13.2@2138.13,2689.24 C13.2@2138.13,2689.24
  Top Layer w30: R12.2@2062.43,2689.17 C13.2@2138.13,2689.24
NetC14_2: C14.2 R13.2 | length 75.7
  Top Layer w30: R13.2@2062.43,2429.94 C14.2@2138.13,2429.94
NetC15_2: C15.2 R14.2 | length 75.7
  Top Layer w30: R14.2@2062.43,1873.9 2138.06,1873.9 C15.2@2138.13,1873.97
NetC16_2: C16.2 R15.2 | length 75.7
  Top Layer w30: R15.2@2062.43,1498.36 C16.2@2138.13,1498.43 C16.2@2138.13,1498.43
NetC17_2: C17.2 R16.2 | length 75.7
  Top Layer w30: R16.2@2062.43,1239.12 C17.2@2138.13,1239.12
NetC18_2: C18.2 R17.2 | length 75.7
  Top Layer w30: R17.2@2062.43,683.09 C18.2@2138.13,683.09
NetC19_2: C19.2 R18.2 | length 75.7
  Top Layer w30: R18.2@2062.43,307.54 2138.06,307.54 C19.2@2138.13,307.61
NetD1_1: D1.1 D2.1 | length 126.3
  Top Layer w20: D2.1@614.88,664.64 620.09,669.85 D1.1@620.09,788.8
NetD3_2: D3.2 R10.1 T1.12 | length 467.5
  Top Layer w50: T1.12@1665,3412.87 1724.87,3412.87 1848.04,3536.04 D3.2@1994.84,3536.04 1994.84,3616.15 R10.1@1999.44,3620.75
NetD4_1: D4.1 R7.1 T1.10 | length 391.1
  Top Layer w50: T1.10@1665,3212.87 1899.22,3212.87 D4.1@2010.17,3323.83
NetD5_2: D5.2 R11.1 T1.9 | length 441.1
  Top Layer w50: T1.9@1665,3112.87 1946.13,3112.87 R11.1@1999.44,3059.56 ; D5.2@1994.84,2980.01 D5.2@1997.96,2983.13 ; D5.2@1999.44,2984.61 R11.1@1999.44,3059.56 ; R11.1@1999.44,3064.72 R11.1@1999.44,3059.56
NetD6_1: D6.1 R12.1 T1.7 | length 500.7
  Top Layer w50: T1.7@1665,2912.87 1723.13,2912.87 1862.05,2773.95 D6.1@2016.33,2773.95 1999.44,2757.06 R12.1@1999.44,2689.17
NetD7_2: D7.2 R13.1 T2.12 | length 467.5
  Top Layer w50: T2.12@1665,2222.06 1721.31,2222.06 1844.48,2345.23 D7.2@1994.84,2345.23 1999.44,2349.83 R13.1@1999.44,2429.94
NetD8_1: D8.1 R8.1 T2.10 | length 340.6
  Top Layer w50: T2.10@1665,2022.06 1946.06,2022.06 R8.1@1988.19,2064.18
NetD9_2: D9.2 R14.1 T2.9 | length 441
  Top Layer w50: T2.9@1665,1922.06 1937.45,1922.06 1985.61,1873.9 R14.1@1999.44,1873.9 1994.84,1869.3 D9.2@1994.84,1789.19
NetD10_1: D10.1 R15.1 T2.7 | length 498.4
  Top Layer w50: T2.7@1665,1722.06 1764.09,1722.06 1906.77,1579.37 D10.1@2012.57,1579.37 ; R15.1@1999.44,1498.36 1999.44,1566.24 D10.1@2012.57,1579.37 ; D10.1@2016.33,1583.14 D10.1@2012.57,1579.37
NetD11_2: D11.2 R16.1 T3.12 | length 505.3
  Top Layer w50: T3.12@1665,1031.24 1723.83,1031.24 1931.71,1239.12 R16.1@1994.84,1239.12 ; D11.2@1994.84,1154.41 R16.1@1994.84,1239.12 ; R16.1@1999.44,1239.12 R16.1@1994.84,1239.12
NetD12_1: D12.1 R9.1 T3.10 | length 443.8
  Top Layer w50: T3.10@1665,831.24 1861.9,831.24 1962.13,931.46 1999.44,931.46 R9.1@1999.44,863.58
NetD13_2: D13.2 R17.1 T3.9 | length 441
  Top Layer w50: T3.9@1665,731.24 1915.7,731.24 1963.85,683.09 R17.1@1999.44,683.09 1994.84,678.48 D13.2@1994.84,598.38
NetD14_1: D14.1 R18.1 T3.7 | length 476.8
  Top Layer w50: T3.7@1665,531.24 1713.52,531.24 1852.44,392.32 D14.1@2016.34,392.32 ; R18.1@1999.44,307.54 D14.1@1999.44,375.42
NetR1_1: R1.1 R2.2 U1.4 | length 304.1
  Top Layer w10: R2.2@352.07,964.94 R1.1@426.74,964.94 426.74,797.76 445.53,778.97 U1.4@445.53,743.32
NetR3_1: R3.1 R4.2 U1.7 | length 202.3
  Top Layer w10: R3.1@170.7,736.79 170.7,668.16 R4.2@169.48,666.94 220.31,666.94 233.69,680.32 U1.7@295.93,680.32
NetR3_2: R3.2 U1.6 | length 72.6
  Top Layer w10: R3.2@233.69,736.79 258.66,711.82 U1.6@295.93,711.82
NetR6_1: R6.1 U1.2 | length 55.2
  Top Layer w10: U1.2@445.53,680.32 R6.1@500.73,680.32
RTN_1: C20.1 C21.1 C32.1 C33.1 C44.1 D15.2 D16.1 J2.2 T1.11 | length 1207.8
  Top Layer w50: T1.11@1665,3312.87 1810.87,3312.87 1938.89,3440.89 2140.91,3440.89 J2.2@2819.77,3440.89
  other v1: 1755,3290 1795,3290 1755,3329.45 1795,3329.45 2241.82,3430 2292.27,3430 2342.73,3430 2393.18,3430 2443.64,3430 2494.09,3430 2544.55,3430 2595,3430
  other v2: 1500,3250 1550,3250 1500,3479.05 1550,3479.05
RTN_2: C22.1 C23.1 C34.1 C35.1 C45.1 D17.2 D18.1 J3.2 T1.8 | length 1207.8
  Top Layer w50: T1.8@1665,3012.87 1797.8,3012.87 1925.83,2884.85 J3.2@2819.77,2884.85
  other v1: 2241.82,2875 2292.27,2875 2342.73,2875 2393.18,2875 2443.64,2875 2494.09,2875 2544.55,2875 2595,2875 1754.96,2993.42 1794.96,2993.42 1754.96,3032.87 1794.96,3032.87
  other v2: 1500,2846.43 1550,2846.43 1500,3075.48 1550,3075.48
